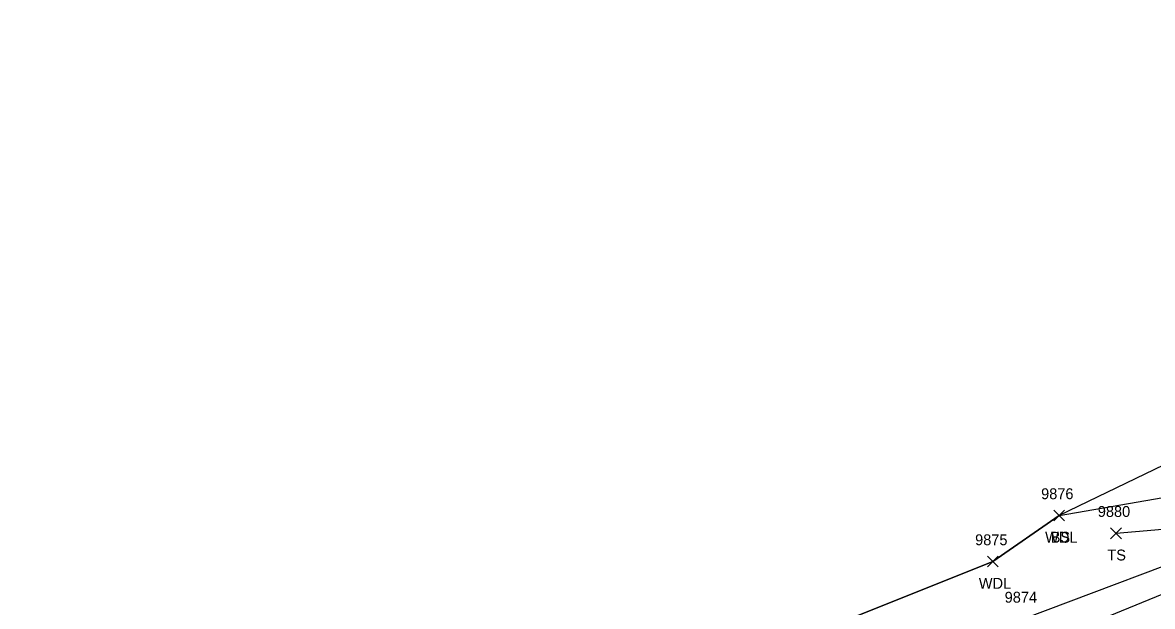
# Model space of a CAD drawing. Extents: x 1651685 to 1653558, y 889533 to 891085.
# Drawn here: x 1651999.4 to 1652207, y 889855.7 to 889963 of the extents above; entities that cross this region are included whole.
import ezdxf

# ---------------------------------------------------------------- set-up
doc = ezdxf.new("R2010")
doc.units = 0
for name, color, linetype in [('L_A', 7, 'Continuous'), ('L_I', 7, 'Continuous'), ('L_TIC', 7, 'Continuous'), ('LAWA', 7, 'Continuous'), ('LELB', 7, 'Continuous'), ('LSOGP', 7, 'Continuous'), ('PET', 7, 'Continuous')]:
    doc.layers.add(name, color=color, linetype=linetype)

msp = doc.modelspace()

# ---------------------------------------------------------------- linework, layer by layer
at = {"layer": 'L_TIC'}
for points in [[(1652188.89, 889871.39), (1652190.89, 889873.39)], [(1652190.89, 889871.39), (1652188.89, 889873.39)], [(1652188.89, 889871.39), (1652190.89, 889873.39)], [(1652190.89, 889871.39), (1652188.89, 889873.39)], [(1652199.34, 889868.13), (1652201.34, 889870.13)], [(1652201.34, 889868.13), (1652199.34, 889870.13)], [(1652176.7, 889862.93), (1652178.7, 889864.93)], [(1652178.7, 889862.93), (1652176.7, 889864.93)]]:
    msp.add_lwpolyline(points, dxfattribs=at)
at = {"layer": 'LAWA'}
msp.add_lwpolyline([(1652130.38, 889845.03), (1652177.7, 889863.93), (1652189.89, 889872.39)], dxfattribs=at)
at = {"layer": 'LELB'}
for points in [[(1652104.14, 889832.31), (1652133.95, 889838.61), (1652183.13, 889853.37), (1652222.17, 889868.05), (1652260.83, 889884.17), (1652274.76, 889892.87), (1652271.19, 889906.55)], [(1652189.89, 889872.39), (1652218.58, 889877.34), (1652257.91, 889893.24), (1652270.25, 889898.05), (1652269.1, 889906.41)], [(1652200.34, 889869.13), (1652220.94, 889870.9), (1652259.54, 889887.95), (1652274.76, 889892.87)]]:
    msp.add_lwpolyline(points, dxfattribs=at)
at = {"layer": 'LSOGP'}
msp.add_lwpolyline([(1652344.51, 889962.98), (1652311.88, 889950.06), (1652319.83, 889936.28), (1652297.31, 889917.06), (1652293.22, 889915.65), (1652288.54, 889913.18), (1652275.12, 889907.88), (1652271.2, 889906.55), (1652269.1, 889906.41), (1652254.49, 889898.49), (1652214.38, 889884.21), (1652189.89, 889872.39), (1652177.7, 889863.92), (1652130.38, 889845.03), (1652128.61, 889848.08), (1652100.57, 889839.31), (1652088.78, 889837.26), (1652079.97, 889838.39), (1652075.93, 889835.91), (1652046.4, 889818.27), (1652039.29, 889812.4), (1652028.35, 889807.39), (1651985.79, 889786.86)], dxfattribs=at)
at = {"layer": 'PET'}
msp.add_lwpolyline([(1651993.09, 889770.39), (1652035.55, 889788.28), (1652064.19, 889800.06), (1652068.27, 889804.89), (1652108.23, 889818.22), (1652137.76, 889829.36), (1652185.37, 889848.31), (1652223.8, 889864.06), (1652262.57, 889880.14), (1652279.91, 889887.76), (1652294.79, 889894.11), (1652333.65, 889912.67), (1652369.12, 889931.53)], dxfattribs=at)

# ---------------------------------------------------------------- texts
at = {"layer": 'L_A'}
for s, p in [('WDL', (1652187.31, 889867.39)), ('BS', (1652188.33, 889867.39)), ('TS', (1652198.75, 889864.13)), ('WDL', (1652175.12, 889858.93))]:
    msp.add_text(s, height=2, dxfattribs=at).set_placement(p)
at = {"layer": 'L_I'}
for s, p in [('9876', (1652186.57, 889875.39)), ('9876', (1652186.57, 889875.39)), ('9880', (1652196.99, 889872.13)), ('9875', (1652174.44, 889866.93)), ('9874', (1652179.87, 889856.37))]:
    msp.add_text(s, height=2, dxfattribs=at).set_placement(p)

doc.saveas('drawing.dxf')
